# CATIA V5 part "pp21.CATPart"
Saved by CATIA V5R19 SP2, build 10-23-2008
Part number: pp21
Bounding box of the stored display mesh (mm): x -9.5 to 9.5, y -197.268 to -122.818, z -25 to 25
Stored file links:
  C:\Users\Welcome\Documents\thinkm2\pp21.CATPart
  C:\Users\Welcome\Documents\thinkm2\Brasmeca.CATProduct
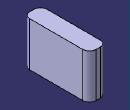
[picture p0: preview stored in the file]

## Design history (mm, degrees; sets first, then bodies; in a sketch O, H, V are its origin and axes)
AxisSystem1: origin (0, 0, 0), X (1, 0, 0), Y (0, 1, 0), Z (0, 0, 1)
Set1
  Plane1: linked copy from another document
Body1 (main body)
  Sketch1 on Plane1, origin (0, 0, 25), H (1, 0, 0), V (0, -1, 0)
    line L1 (-3.0417, 122.8182) -> (1.8906, 122.8182)
    line L2 (9.5, 130.4276) -> (9.5, 190.7068)
    line L3 (2.9383, 197.2685) -> (-2.2068, 197.2685)
    line L4 (-9.5, 189.9753) -> (-9.5, 129.2765)
    arc A1 centre (2.9383, 190.7068) radius 6.5617 from (9.5, 190.7068) to (2.9383, 197.2685) ccw
    arc A2 centre (-2.2068, 189.9753) radius 7.2932 from (-9.5, 189.9753) to (-2.2068, 197.2685) cw
    arc A3 centre (1.8906, 130.4276) radius 7.6094 from (9.5, 130.4276) to (1.8906, 122.8182) cw
    arc A4 centre (-3.0417, 129.2765) radius 6.4583 from (-3.0417, 122.8182) to (-9.5, 129.2765) cw
    distance L3 L1 = 74.4503
    distance L3 H = 197.2685
    distance L2 L4 = 19
    distance L2 V = 9.5
  Pad1: profile Sketch1, direction (0, 0, -1), length 50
